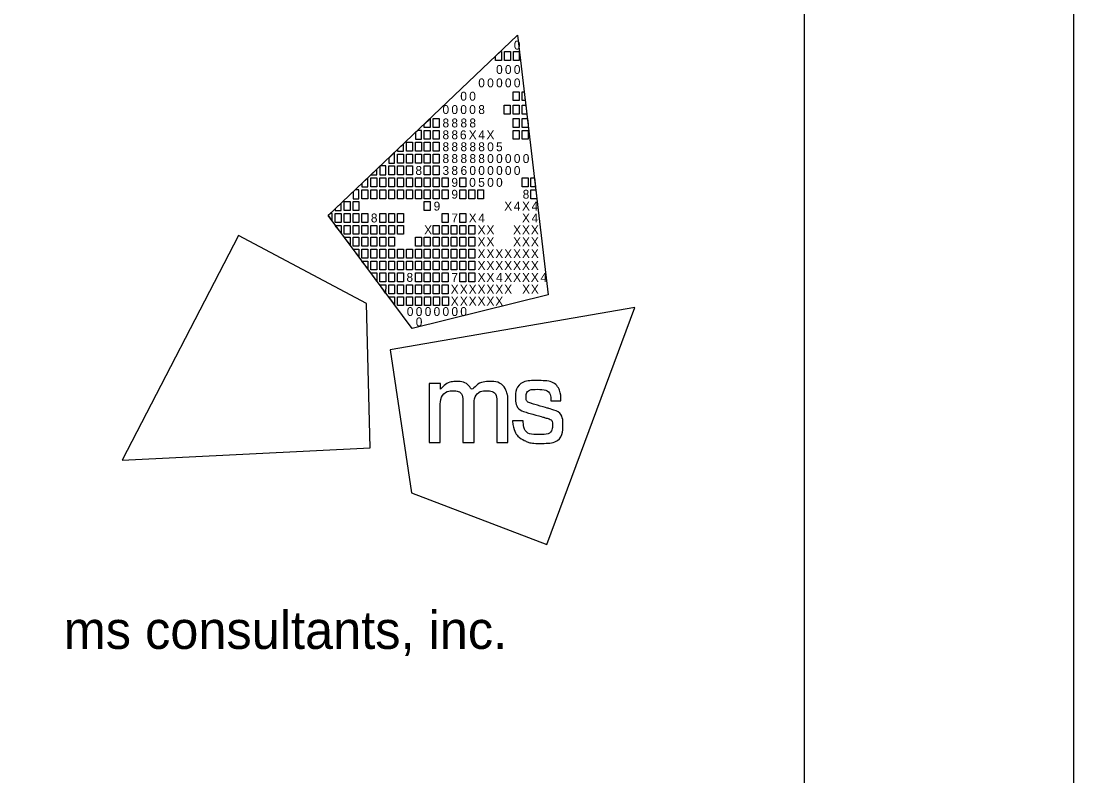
# Model space of a CAD drawing. Extents: x 0 to 49.8, y -1.8 to 22.
# Drawn here: x 32.048 to 34, y 2.714 to 4.112 of the extents above; entities that cross this region are included whole.
import ezdxf

# ---------------------------------------------------------------- set-up
doc = ezdxf.new("R2010")
doc.units = 0
for name, color, linetype in [('SH_Border', 7, 'Continuous'), ('SH_Cut_Line', 7, 'Continuous'), ('SH_Data', 7, 'Continuous')]:
    doc.layers.add(name, color=color, linetype=linetype)

msp = doc.modelspace()

# ---------------------------------------------------------------- linework, layer by layer
at = {"layer": 'SH_Border'}
msp.add_lwpolyline([(1.5, 21.5), (33.5, 21.5), (33.5, 0.5), (1.5, 0.5)], close=True, dxfattribs=at)
at = {"layer": 'SH_Cut_Line'}
msp.add_lwpolyline([(0, 0), (34, 0), (34, 22), (0, 22)], close=True, dxfattribs=at)
at = {"layer": 'SH_Data'}
for p, q in [((32.6175, 3.7519), (32.9688, 4.0861)), ((32.9688, 4.0861), (32.9688, 4.0861)), ((32.9688, 4.0861), (33.0253, 3.6052)), ((32.773, 3.543), (32.6175, 3.7519)), ((33.0253, 3.6052), (32.773, 3.543)), ((32.75, 3.5), (32.75, 3.5))]:
    msp.add_line(p, q, dxfattribs=at)
for points in [[(32.9279, 4.0472), (32.9369, 4.0558), (32.9389, 4.0558), (32.9389, 4.0393), (32.9279, 4.0393)], [(32.9444, 4.0558), (32.9554, 4.0558), (32.9554, 4.0393), (32.9444, 4.0393)], [(32.9609, 4.0558), (32.9719, 4.0558), (32.9719, 4.0393), (32.9609, 4.0393)], [(32.9606, 3.9815), (32.9716, 3.9815), (32.9716, 3.965), (32.9606, 3.965)], [(32.9771, 3.9815), (32.9811, 3.9815), (32.983, 3.965), (32.9771, 3.965)], [(32.9441, 3.9567), (32.9551, 3.9567), (32.9551, 3.9402), (32.9441, 3.9402)], [(32.9606, 3.9567), (32.9716, 3.9567), (32.9716, 3.9402), (32.9606, 3.9402)], [(32.9771, 3.9567), (32.984, 3.9567), (32.9859, 3.9402), (32.9771, 3.9402)], [(32.7953, 3.9211), (32.8064, 3.9316), (32.8064, 3.9154), (32.7953, 3.9154)], [(32.8123, 3.9319), (32.8233, 3.9319), (32.8233, 3.9154), (32.8123, 3.9154)], [(32.9606, 3.9319), (32.9716, 3.9319), (32.9716, 3.9154), (32.9606, 3.9154)], [(32.9771, 3.9319), (32.9869, 3.9319), (32.9881, 3.9218), (32.9881, 3.9154), (32.9771, 3.9154)], [(32.7958, 3.9099), (32.8068, 3.9099), (32.8068, 3.8934), (32.7958, 3.8934)], [(32.8123, 3.9099), (32.8233, 3.9099), (32.8233, 3.8934), (32.8123, 3.8934)], [(32.9606, 3.9099), (32.9716, 3.9099), (32.9716, 3.8934), (32.9606, 3.8934)], [(32.9771, 3.9099), (32.9881, 3.9099), (32.9881, 3.8934), (32.9771, 3.8934)], [(32.7627, 3.8879), (32.7737, 3.8879), (32.7737, 3.8714), (32.7627, 3.8714)], [(32.7793, 3.8879), (32.7903, 3.8879), (32.7903, 3.8714), (32.7793, 3.8714)], [(32.7958, 3.8879), (32.8068, 3.8879), (32.8068, 3.8714), (32.7958, 3.8714)], [(32.8123, 3.8879), (32.8233, 3.8879), (32.8233, 3.8714), (32.8123, 3.8714)], [(32.7462, 3.8659), (32.7572, 3.8659), (32.7572, 3.8494), (32.7462, 3.8494)], [(32.7627, 3.8659), (32.7737, 3.8659), (32.7737, 3.8494), (32.7627, 3.8494)], [(32.7793, 3.8659), (32.7903, 3.8659), (32.7903, 3.8494), (32.7793, 3.8494)], [(32.7958, 3.8659), (32.8068, 3.8659), (32.8068, 3.8494), (32.7958, 3.8494)], [(32.8123, 3.8659), (32.8233, 3.8659), (32.8233, 3.8494), (32.8123, 3.8494)], [(32.7297, 3.8439), (32.7407, 3.8439), (32.7407, 3.8273), (32.7297, 3.8273)], [(32.7462, 3.8439), (32.7572, 3.8439), (32.7572, 3.8273), (32.7462, 3.8273)], [(32.7627, 3.8439), (32.7737, 3.8439), (32.7737, 3.8273), (32.7627, 3.8273)], [(32.7958, 3.8439), (32.8068, 3.8439), (32.8068, 3.8273), (32.7958, 3.8273)], [(32.8123, 3.8439), (32.8233, 3.8439), (32.8233, 3.8273), (32.8123, 3.8273)], [(32.6967, 3.8218), (32.7077, 3.8218), (32.7077, 3.8053), (32.6967, 3.8053)], [(32.7132, 3.8218), (32.7242, 3.8218), (32.7242, 3.8053), (32.7132, 3.8053)], [(32.7297, 3.8218), (32.7407, 3.8218), (32.7407, 3.8053), (32.7297, 3.8053)], [(32.7462, 3.8218), (32.7572, 3.8218), (32.7572, 3.8053), (32.7462, 3.8053)], [(32.7627, 3.8218), (32.7737, 3.8218), (32.7737, 3.8053), (32.7627, 3.8053)], [(32.7793, 3.8218), (32.7903, 3.8218), (32.7903, 3.8053), (32.7793, 3.8053)], [(32.7958, 3.8218), (32.8068, 3.8218), (32.8068, 3.8053), (32.7958, 3.8053)], [(32.8123, 3.8218), (32.8233, 3.8218), (32.8233, 3.8053), (32.8123, 3.8053)], [(32.8288, 3.8218), (32.8398, 3.8218), (32.8398, 3.8053), (32.8288, 3.8053)], [(32.8618, 3.8218), (32.8728, 3.8218), (32.8728, 3.8053), (32.8618, 3.8053)], [(32.9771, 3.8218), (32.9881, 3.8218), (32.9881, 3.8053), (32.9771, 3.8053)], [(32.9935, 3.8218), (32.9998, 3.8218), (33.0018, 3.8053), (32.9935, 3.8053)], [(32.6802, 3.7998), (32.6912, 3.7998), (32.6912, 3.7833), (32.6802, 3.7833)], [(32.6967, 3.7998), (32.7077, 3.7998), (32.7077, 3.7833), (32.6967, 3.7833)], [(32.7132, 3.7998), (32.7242, 3.7998), (32.7242, 3.7833), (32.7132, 3.7833)], [(32.7297, 3.7998), (32.7407, 3.7998), (32.7407, 3.7833), (32.7297, 3.7833)], [(32.7462, 3.7998), (32.7572, 3.7998), (32.7572, 3.7833), (32.7462, 3.7833)], [(32.7627, 3.7998), (32.7737, 3.7998), (32.7737, 3.7833), (32.7627, 3.7833)], [(32.7793, 3.7998), (32.7903, 3.7998), (32.7903, 3.7833), (32.7793, 3.7833)], [(32.7958, 3.7998), (32.8068, 3.7998), (32.8068, 3.7833), (32.7958, 3.7833)], [(32.8123, 3.7998), (32.8233, 3.7998), (32.8233, 3.7833), (32.8123, 3.7833)], [(32.8288, 3.7998), (32.8398, 3.7998), (32.8398, 3.7833), (32.8288, 3.7833)], [(32.8618, 3.7998), (32.8728, 3.7998), (32.8728, 3.7833), (32.8618, 3.7833)], [(32.8783, 3.7998), (32.8893, 3.7998), (32.8893, 3.7833), (32.8783, 3.7833)], [(32.8947, 3.7998), (32.9057, 3.7998), (32.9057, 3.7833), (32.8947, 3.7833)], [(32.9935, 3.7998), (33.0024, 3.7998), (33.0044, 3.7833), (32.9935, 3.7833)], [(32.6471, 3.7778), (32.6581, 3.7778), (32.6581, 3.7613), (32.6471, 3.7613)], [(32.6637, 3.7778), (32.6747, 3.7778), (32.6747, 3.7613), (32.6637, 3.7613)], [(32.7958, 3.7778), (32.8068, 3.7778), (32.8068, 3.7613), (32.7958, 3.7613)], [(32.6306, 3.7558), (32.6416, 3.7558), (32.6416, 3.7393), (32.6306, 3.7393)], [(32.6471, 3.7558), (32.6581, 3.7558), (32.6581, 3.7393), (32.6471, 3.7393)], [(32.6637, 3.7558), (32.6747, 3.7558), (32.6747, 3.7393), (32.6637, 3.7393)], [(32.6802, 3.7558), (32.6912, 3.7558), (32.6912, 3.7393), (32.6802, 3.7393)], [(32.7132, 3.7558), (32.7242, 3.7558), (32.7242, 3.7393), (32.7132, 3.7393)], [(32.7297, 3.7558), (32.7407, 3.7558), (32.7407, 3.7393), (32.7297, 3.7393)], [(32.7462, 3.7558), (32.7572, 3.7558), (32.7572, 3.7393), (32.7462, 3.7393)], [(32.8288, 3.7558), (32.8398, 3.7558), (32.8398, 3.7393), (32.8288, 3.7393)], [(32.8618, 3.7558), (32.8728, 3.7558), (32.8728, 3.7393), (32.8618, 3.7393)], [(32.6306, 3.7338), (32.6416, 3.7338), (32.6416, 3.72)], [(32.6471, 3.7338), (32.6581, 3.7338), (32.6581, 3.7173), (32.6471, 3.7173)], [(32.6637, 3.7338), (32.6747, 3.7338), (32.6747, 3.7173), (32.6637, 3.7173)], [(32.6802, 3.7338), (32.6912, 3.7338), (32.6912, 3.7173), (32.6802, 3.7173)], [(32.6967, 3.7338), (32.7077, 3.7338), (32.7077, 3.7173), (32.6967, 3.7173)], [(32.7132, 3.7338), (32.7242, 3.7338), (32.7242, 3.7173), (32.7132, 3.7173)], [(32.7297, 3.7338), (32.7407, 3.7338), (32.7407, 3.7173), (32.7297, 3.7173)], [(32.7462, 3.7338), (32.7572, 3.7338), (32.7572, 3.7173), (32.7462, 3.7173)], [(32.8123, 3.7338), (32.8233, 3.7338), (32.8233, 3.7173), (32.8123, 3.7173)], [(32.8288, 3.7338), (32.8398, 3.7338), (32.8398, 3.7173), (32.8288, 3.7173)], [(32.8453, 3.7338), (32.8563, 3.7338), (32.8563, 3.7173), (32.8453, 3.7173)], [(32.8618, 3.7338), (32.8728, 3.7338), (32.8728, 3.7173), (32.8618, 3.7173)], [(32.8783, 3.7338), (32.8893, 3.7338), (32.8893, 3.7173), (32.8783, 3.7173)], [(32.6471, 3.7117), (32.6581, 3.7117), (32.6581, 3.698)], [(32.6637, 3.7117), (32.6747, 3.7117), (32.6747, 3.6952), (32.6637, 3.6952)], [(32.6802, 3.7117), (32.6912, 3.7117), (32.6912, 3.6952), (32.6802, 3.6952)], [(32.6967, 3.7117), (32.7077, 3.7117), (32.7077, 3.6952), (32.6967, 3.6952)], [(32.7132, 3.7117), (32.7242, 3.7117), (32.7242, 3.6952), (32.7132, 3.6952)], [(32.7297, 3.7117), (32.7407, 3.7117), (32.7407, 3.6952), (32.7297, 3.6952)], [(32.7793, 3.7117), (32.7903, 3.7117), (32.7903, 3.6952), (32.7793, 3.6952)], [(32.7958, 3.7117), (32.8068, 3.7117), (32.8068, 3.6952), (32.7958, 3.6952)], [(32.8123, 3.7117), (32.8233, 3.7117), (32.8233, 3.6952), (32.8123, 3.6952)], [(32.8288, 3.7117), (32.8398, 3.7117), (32.8398, 3.6952), (32.8288, 3.6952)], [(32.8453, 3.7117), (32.8563, 3.7117), (32.8563, 3.6952), (32.8453, 3.6952)], [(32.8618, 3.7117), (32.8728, 3.7117), (32.8728, 3.6952), (32.8618, 3.6952)], [(32.8783, 3.7117), (32.8893, 3.7117), (32.8893, 3.6952), (32.8783, 3.6952)], [(32.6637, 3.6897), (32.6747, 3.6897), (32.6747, 3.676)], [(32.6747, 3.6897), (32.6747, 3.6897), (32.6747, 3.6897)], [(32.6802, 3.6897), (32.6912, 3.6897), (32.6912, 3.6732), (32.6802, 3.6732)], [(32.6967, 3.6897), (32.7077, 3.6897), (32.7077, 3.6732), (32.6967, 3.6732)], [(32.7132, 3.6897), (32.7242, 3.6897), (32.7242, 3.6732), (32.7132, 3.6732)], [(32.7297, 3.6897), (32.7407, 3.6897), (32.7407, 3.6732), (32.7297, 3.6732)], [(32.7462, 3.6897), (32.7572, 3.6897), (32.7572, 3.6732), (32.7462, 3.6732)], [(32.7627, 3.6897), (32.7737, 3.6897), (32.7737, 3.6732), (32.7627, 3.6732)], [(32.7793, 3.6897), (32.7903, 3.6897), (32.7903, 3.6732), (32.7793, 3.6732)], [(32.7958, 3.6897), (32.8068, 3.6897), (32.8068, 3.6732), (32.7958, 3.6732)], [(32.8123, 3.6897), (32.8233, 3.6897), (32.8233, 3.6732), (32.8123, 3.6732)], [(32.8288, 3.6897), (32.8398, 3.6897), (32.8398, 3.6732), (32.8288, 3.6732)], [(32.8453, 3.6897), (32.8563, 3.6897), (32.8563, 3.6732), (32.8453, 3.6732)], [(32.8618, 3.6897), (32.8728, 3.6897), (32.8728, 3.6732), (32.8618, 3.6732)], [(32.8783, 3.6897), (32.8893, 3.6897), (32.8893, 3.6732), (32.8783, 3.6732)], [(32.6802, 3.6677), (32.6912, 3.6677), (32.6912, 3.654)], [(32.6967, 3.6677), (32.7077, 3.6677), (32.7077, 3.6512), (32.6967, 3.6512)], [(32.7132, 3.6677), (32.7242, 3.6677), (32.7242, 3.6512), (32.7132, 3.6512)], [(32.7297, 3.6677), (32.7407, 3.6677), (32.7407, 3.6512), (32.7297, 3.6512)], [(32.7462, 3.6677), (32.7572, 3.6677), (32.7572, 3.6512), (32.7462, 3.6512)], [(32.7627, 3.6677), (32.7737, 3.6677), (32.7737, 3.6512), (32.7627, 3.6512)], [(32.7793, 3.6677), (32.7903, 3.6677), (32.7903, 3.6512), (32.7793, 3.6512)], [(32.7958, 3.6677), (32.8068, 3.6677), (32.8068, 3.6512), (32.7958, 3.6512)], [(32.8123, 3.6677), (32.8233, 3.6677), (32.8233, 3.6512), (32.8123, 3.6512)], [(32.8288, 3.6677), (32.8398, 3.6677), (32.8398, 3.6512), (32.8288, 3.6512)], [(32.8453, 3.6677), (32.8563, 3.6677), (32.8563, 3.6512), (32.8453, 3.6512)], [(32.8618, 3.6677), (32.8728, 3.6677), (32.8728, 3.6512), (32.8618, 3.6512)], [(32.8783, 3.6677), (32.8893, 3.6677), (32.8893, 3.6512), (32.8783, 3.6512)], [(32.7077, 3.6305), (32.6965, 3.6457), (32.7077, 3.6457)], [(32.7132, 3.6457), (32.7242, 3.6457), (32.7242, 3.6292), (32.7132, 3.6292)], [(32.7297, 3.6457), (32.7407, 3.6457), (32.7407, 3.6292), (32.7297, 3.6292)], [(32.7462, 3.6457), (32.7572, 3.6457), (32.7572, 3.6292), (32.7462, 3.6292)], [(32.7793, 3.6457), (32.7903, 3.6457), (32.7903, 3.6292), (32.7793, 3.6292)], [(32.7958, 3.6457), (32.8068, 3.6457), (32.8068, 3.6292), (32.7958, 3.6292)], [(32.8123, 3.6457), (32.8233, 3.6457), (32.8233, 3.6292), (32.8123, 3.6292)], [(32.8288, 3.6457), (32.8398, 3.6457), (32.8398, 3.6292), (32.8288, 3.6292)], [(32.8618, 3.6457), (32.8728, 3.6457), (32.8728, 3.6292), (32.8618, 3.6292)], [(32.8783, 3.6457), (32.8893, 3.6457), (32.8893, 3.6292), (32.8783, 3.6292)], [(32.724, 3.6082), (32.7132, 3.6237), (32.7242, 3.6237)], [(32.7297, 3.6237), (32.7407, 3.6237), (32.7407, 3.6072), (32.7297, 3.6072)], [(32.7462, 3.6237), (32.7572, 3.6237), (32.7572, 3.6072), (32.7462, 3.6072)], [(32.7627, 3.6237), (32.7737, 3.6237), (32.7737, 3.6072), (32.7627, 3.6072)], [(32.7793, 3.6237), (32.7903, 3.6237), (32.7903, 3.6072), (32.7793, 3.6072)], [(32.7958, 3.6237), (32.8068, 3.6237), (32.8068, 3.6072), (32.7958, 3.6072)], [(32.8123, 3.6237), (32.8233, 3.6237), (32.8233, 3.6072), (32.8123, 3.6072)], [(32.8288, 3.6237), (32.8398, 3.6237), (32.8398, 3.6072), (32.8288, 3.6072)], [(32.7302, 3.6017), (32.7407, 3.6017), (32.7408, 3.5875)], [(32.7463, 3.6017), (32.7573, 3.6017), (32.7573, 3.5852), (32.7463, 3.5852)], [(32.763, 3.6017), (32.774, 3.6017), (32.774, 3.5852), (32.763, 3.5852)], [(32.7794, 3.6017), (32.7904, 3.6017), (32.7904, 3.5852), (32.7794, 3.5852)], [(32.796, 3.6017), (32.807, 3.6017), (32.807, 3.5852), (32.796, 3.5852)], [(32.8129, 3.6017), (32.8239, 3.6017), (32.8239, 3.5851), (32.8129, 3.5851)], [(32.8296, 3.6017), (32.8406, 3.6017), (32.8406, 3.5851), (32.8296, 3.5851)]]:
    msp.add_lwpolyline(points, close=True, dxfattribs=at)
for points in [[(32.7903, 3.9099), (32.7836, 3.9099), (32.7793, 3.9058), (32.7793, 3.8934), (32.7903, 3.8934), (32.7903, 3.9099)], [(32.7572, 3.8849), (32.7462, 3.8744), (32.7462, 3.8714), (32.7572, 3.8714), (32.7572, 3.8849)], [(32.7407, 3.8691), (32.7297, 3.8587), (32.7297, 3.8494), (32.7407, 3.8494), (32.7407, 3.8691)], [(32.7077, 3.8377), (32.6968, 3.8273), (32.7077, 3.8273), (32.7077, 3.8377)], [(32.7242, 3.8439), (32.7141, 3.8439), (32.7132, 3.843), (32.7132, 3.8273), (32.7242, 3.8273), (32.7242, 3.8439)], [(32.6912, 3.822), (32.6802, 3.8115), (32.6802, 3.8053), (32.6912, 3.8053), (32.6912, 3.822)], [(32.6747, 3.7998), (32.6679, 3.7998), (32.6637, 3.7958), (32.6637, 3.7833), (32.6747, 3.7833), (32.6747, 3.7998)], [(32.6416, 3.7749), (32.6306, 3.7644), (32.6306, 3.7613), (32.6416, 3.7613), (32.6416, 3.7749)], [(32.6251, 3.7558), (32.6216, 3.7558), (32.6175, 3.7519), (32.6251, 3.7417), (32.6251, 3.7558)], [(32.4512, 3.7149), (32.2359, 3.2988), (32.6956, 3.3215), (32.6884, 3.5892), (32.4512, 3.7149)], [(33.0229, 3.1422), (33.1859, 3.5814), (32.7324, 3.5029), (32.7722, 3.2381), (33.0229, 3.1422)]]:
    msp.add_lwpolyline(points, dxfattribs=at)
for points in [[(32.8048, 3.3315), (32.8048, 3.3315), (32.8048, 3.4409), (32.8048, 3.4409), (32.8048, 3.4409), (32.8255, 3.4409), (32.8255, 3.4409), (32.8255, 3.4409), (32.8255, 3.4297), (32.8255, 3.4297), (32.8346, 3.4399), (32.8457, 3.4445), (32.8555, 3.4445), (32.8688, 3.4445), (32.8791, 3.4372), (32.8837, 3.4266), (32.8915, 3.4381), (32.905, 3.4446), (32.9166, 3.4446), (32.9325, 3.4446), (32.9451, 3.435), (32.9494, 3.4213), (32.9494, 3.4212), (32.9494, 3.4212), (32.9494, 3.4212), (32.9501, 3.419), (32.9506, 3.4172), (32.9506, 3.4071), (32.9506, 3.4071), (32.9506, 3.3314), (32.9506, 3.3314), (32.9506, 3.3314), (32.9303, 3.3314), (32.9303, 3.3314), (32.9303, 3.3314), (32.9303, 3.4048), (32.9303, 3.4048), (32.9303, 3.4201), (32.9219, 3.4274), (32.911, 3.4274), (32.8995, 3.4274), (32.8879, 3.4171), (32.8879, 3.4001), (32.8879, 3.4001), (32.8879, 3.3315), (32.8879, 3.3315), (32.8879, 3.3315), (32.8674, 3.3315), (32.8674, 3.3315), (32.8674, 3.3315), (32.8674, 3.4059), (32.8674, 3.4059), (32.8674, 3.4203), (32.8588, 3.4274), (32.8496, 3.4274), (32.8384, 3.4274), (32.8254, 3.417), (32.8254, 3.3962), (32.8254, 3.3962), (32.8254, 3.3315), (32.8254, 3.3315), (32.8254, 3.3315), (32.8048, 3.3315), (32.8048, 3.3315)], [(32.9595, 3.3709), (32.9595, 3.3709), (32.9595, 3.3717), (32.9595, 3.3717), (32.9595, 3.3717), (32.9603, 3.3717), (32.9603, 3.3717), (32.9603, 3.3717), (32.9783, 3.3717), (32.9783, 3.3717), (32.9783, 3.3717), (32.9789, 3.3717), (32.9789, 3.3717), (32.9789, 3.3717), (32.979, 3.371), (32.979, 3.371), (32.9803, 3.3554), (32.9887, 3.346), (33.009, 3.346), (33.0273, 3.346), (33.0333, 3.3554), (33.0333, 3.3631), (33.0333, 3.3732), (33.0256, 3.3758), (33.0175, 3.378), (33.0175, 3.378), (32.987, 3.3867), (32.987, 3.3867), (32.972, 3.3909), (32.9648, 3.4019), (32.9648, 3.4142), (32.9648, 3.4303), (32.9768, 3.4462), (33.0052, 3.4462), (33.0348, 3.4462), (33.0489, 3.4285), (33.0489, 3.4095), (33.0489, 3.4095), (33.0489, 3.4087), (33.0489, 3.4087), (33.0489, 3.4087), (33.0482, 3.4087), (33.0482, 3.4087), (33.0482, 3.4087), (33.0312, 3.4087), (33.0312, 3.4087), (33.0312, 3.4087), (33.0305, 3.4087), (33.0305, 3.4087), (33.0305, 3.4087), (33.0305, 3.4094), (33.0305, 3.4094), (33.0301, 3.4208), (33.0226, 3.43), (33.0056, 3.43), (32.9891, 3.43), (32.9843, 3.4218), (32.9843, 3.4157), (32.9843, 3.4108), (32.9869, 3.4059), (32.9959, 3.4033), (32.9959, 3.4033), (33.0255, 3.3948), (33.0255, 3.3948), (33.0462, 3.3889), (33.0527, 3.3777), (33.0527, 3.3639), (33.0527, 3.3462), (33.041, 3.3298), (33.0087, 3.3298), (32.9952, 3.3298), (32.9877, 3.3321), (32.9823, 3.3348), (32.969, 3.3414), (32.9609, 3.3536), (32.9595, 3.3709)]]:
    msp.add_open_spline(points, degree=3, dxfattribs=at)

# ---------------------------------------------------------------- texts
for s, height, p in [('0', 0.0165, (32.9617, 4.0597)), ('0', 0.0165, (32.9288, 4.0145)), ('0', 0.0165, (32.9452, 4.0145)), ('0', 0.0165, (32.9617, 4.0145)), ('0', 0.0165, (32.8958, 3.9897)), ('0', 0.0165, (32.9123, 3.9897)), ('0', 0.0165, (32.9288, 3.9897)), ('0', 0.0165, (32.9452, 3.9897)), ('0', 0.0165, (32.9617, 3.9897)), ('0', 0.0165, (32.8625, 3.965)), ('0', 0.0165, (32.879, 3.965)), ('0', 0.0165, (32.8295, 3.9402)), ('0', 0.0165, (32.846, 3.9402)), ('0', 0.0165, (32.8625, 3.9402)), ('0', 0.0165, (32.879, 3.9402)), ('8', 0.0165, (32.8958, 3.9402)), ('8', 0.0165, (32.8295, 3.9154)), ('8', 0.0165, (32.846, 3.9154)), ('8', 0.0165, (32.8628, 3.9154)), ('8', 0.0165, (32.8793, 3.9154)), ('8', 0.0165, (32.8295, 3.8934)), ('8', 0.0165, (32.846, 3.8934)), ('6', 0.0165, (32.8618, 3.8934)), ('X', 0.0165, (32.8781, 3.8934)), ('4', 0.0165, (32.8958, 3.8934)), ('X', 0.0165, (32.911, 3.8934)), ('8', 0.0165, (32.8295, 3.8713)), ('8', 0.0165, (32.846, 3.8713)), ('8', 0.0165, (32.8628, 3.8713)), ('8', 0.0165, (32.8794, 3.8713)), ('8', 0.0165, (32.8958, 3.8713)), ('0', 0.0165, (32.9123, 3.8713)), ('5', 0.0165, (32.9287, 3.8713)), ('8', 0.0165, (32.8295, 3.8494)), ('8', 0.0165, (32.846, 3.8494)), ('8', 0.0165, (32.8628, 3.8494)), ('8', 0.0165, (32.8794, 3.8494)), ('8', 0.0165, (32.8958, 3.8494)), ('0', 0.0165, (32.9123, 3.8494)), ('0', 0.0165, (32.9288, 3.8494)), ('0', 0.0165, (32.9452, 3.8494)), ('0', 0.0165, (32.9617, 3.8494)), ('0', 0.0165, (32.9782, 3.8494)), ('8', 0.0165, (32.7793, 3.8273)), ('3', 0.0165, (32.8295, 3.8273)), ('8', 0.0165, (32.846, 3.8273)), ('6', 0.0165, (32.8629, 3.8273)), ('0', 0.0165, (32.8793, 3.8273)), ('0', 0.0165, (32.8958, 3.8273)), ('0', 0.0165, (32.9123, 3.8273)), ('0', 0.0165, (32.9288, 3.8273)), ('0', 0.0165, (32.9452, 3.8273)), ('0', 0.0165, (32.9617, 3.8273)), ('9', 0.0165, (32.846, 3.8053)), ('0', 0.0165, (32.879, 3.8053)), ('5', 0.0165, (32.8957, 3.8053)), ('0', 0.0165, (32.9123, 3.8053)), ('0', 0.0165, (32.9288, 3.8053)), ('9', 0.0165, (32.846, 3.7833)), ('8', 0.0165, (32.9781, 3.7833)), ('9', 0.0165, (32.813, 3.7613)), ('X', 0.0165, (32.9439, 3.7613)), ('4', 0.0165, (32.9617, 3.7613)), ('X', 0.0165, (32.9769, 3.7613)), ('4', 0.0165, (32.9946, 3.7613)), ('8', 0.0165, (32.6967, 3.7393)), ('7', 0.0165, (32.846, 3.7393)), ('X', 0.0165, (32.8781, 3.7393)), ('4', 0.0165, (32.8958, 3.7393)), ('X', 0.0165, (32.9769, 3.7393)), ('4', 0.0165, (32.9946, 3.7393)), ('X', 0.0165, (32.7955, 3.7173)), ('X', 0.0165, (32.8945, 3.7173)), ('X', 0.0165, (32.911, 3.7173)), ('X', 0.0165, (32.9604, 3.7173)), ('X', 0.0165, (32.9769, 3.7173)), ('X', 0.0165, (32.9933, 3.7173)), ('X', 0.0165, (32.8945, 3.6952)), ('X', 0.0165, (32.911, 3.6952)), ('X', 0.0165, (32.9604, 3.6952)), ('X', 0.0165, (32.9769, 3.6952)), ('X', 0.0165, (32.9933, 3.6952)), ('X', 0.0165, (32.8945, 3.6732)), ('X', 0.0165, (32.911, 3.6732)), ('X', 0.0165, (32.9274, 3.6732)), ('X', 0.0165, (32.9439, 3.6732)), ('X', 0.0165, (32.9604, 3.6732)), ('X', 0.0165, (32.9769, 3.6732)), ('X', 0.0165, (32.9933, 3.6732)), ('X', 0.0165, (32.8945, 3.6512)), ('X', 0.0165, (32.911, 3.6512)), ('X', 0.0165, (32.9274, 3.6512)), ('X', 0.0165, (32.9439, 3.6512)), ('X', 0.0165, (32.9604, 3.6512)), ('X', 0.0165, (32.9769, 3.6512)), ('X', 0.0165, (32.9933, 3.6512)), ('8', 0.0165, (32.7627, 3.6292)), ('7', 0.0165, (32.846, 3.6292)), ('X', 0.0165, (32.8945, 3.6292)), ('X', 0.0165, (32.911, 3.6292)), ('4', 0.0165, (32.9288, 3.6292)), ('X', 0.0165, (32.9439, 3.6292)), ('X', 0.0165, (32.9604, 3.6292)), ('X', 0.0165, (32.9769, 3.6292)), ('X', 0.0165, (32.9933, 3.6292)), ('4', 0.0165, (33.0111, 3.6292)), ('X', 0.0165, (32.8447, 3.6072)), ('X', 0.0165, (32.8616, 3.6072)), ('X', 0.0165, (32.878, 3.6072)), ('X', 0.0165, (32.8945, 3.6072)), ('X', 0.0165, (32.911, 3.6072)), ('X', 0.0165, (32.9274, 3.6072)), ('X', 0.0165, (32.9439, 3.6072)), ('X', 0.0165, (32.9771, 3.6072)), ('X', 0.0165, (32.9933, 3.6072)), ('X', 0.0165, (32.8447, 3.5851)), ('X', 0.0165, (32.8616, 3.5851)), ('X', 0.0165, (32.878, 3.5851)), ('X', 0.0165, (32.8945, 3.5851)), ('X', 0.0165, (32.911, 3.5851)), ('X', 0.0165, (32.9274, 3.5851)), ('0', 0.0165, (32.7634, 3.5659)), ('0', 0.0165, (32.7799, 3.5659)), ('0', 0.0165, (32.7965, 3.5659)), ('0', 0.0165, (32.813, 3.5659)), ('0', 0.0165, (32.8295, 3.5659)), ('0', 0.0165, (32.846, 3.5659)), ('0', 0.0165, (32.8625, 3.5659)), ('0', 0.0165, (32.7799, 3.5467)), ('ms consultants, inc.', 0.07, (32.1273, 2.9489))]:
    msp.add_text(s, height=height, rotation=360, dxfattribs=at).set_placement(p)

doc.saveas('drawing.dxf')
